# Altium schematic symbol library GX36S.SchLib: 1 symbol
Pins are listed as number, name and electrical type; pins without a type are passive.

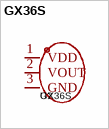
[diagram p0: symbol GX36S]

## GX36S
designator U?
footprint SOT-23_L2.9-W1.3-P1.90-LS2.4-BR
pins: 1 VDD, 2 VOUT, 3 GND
